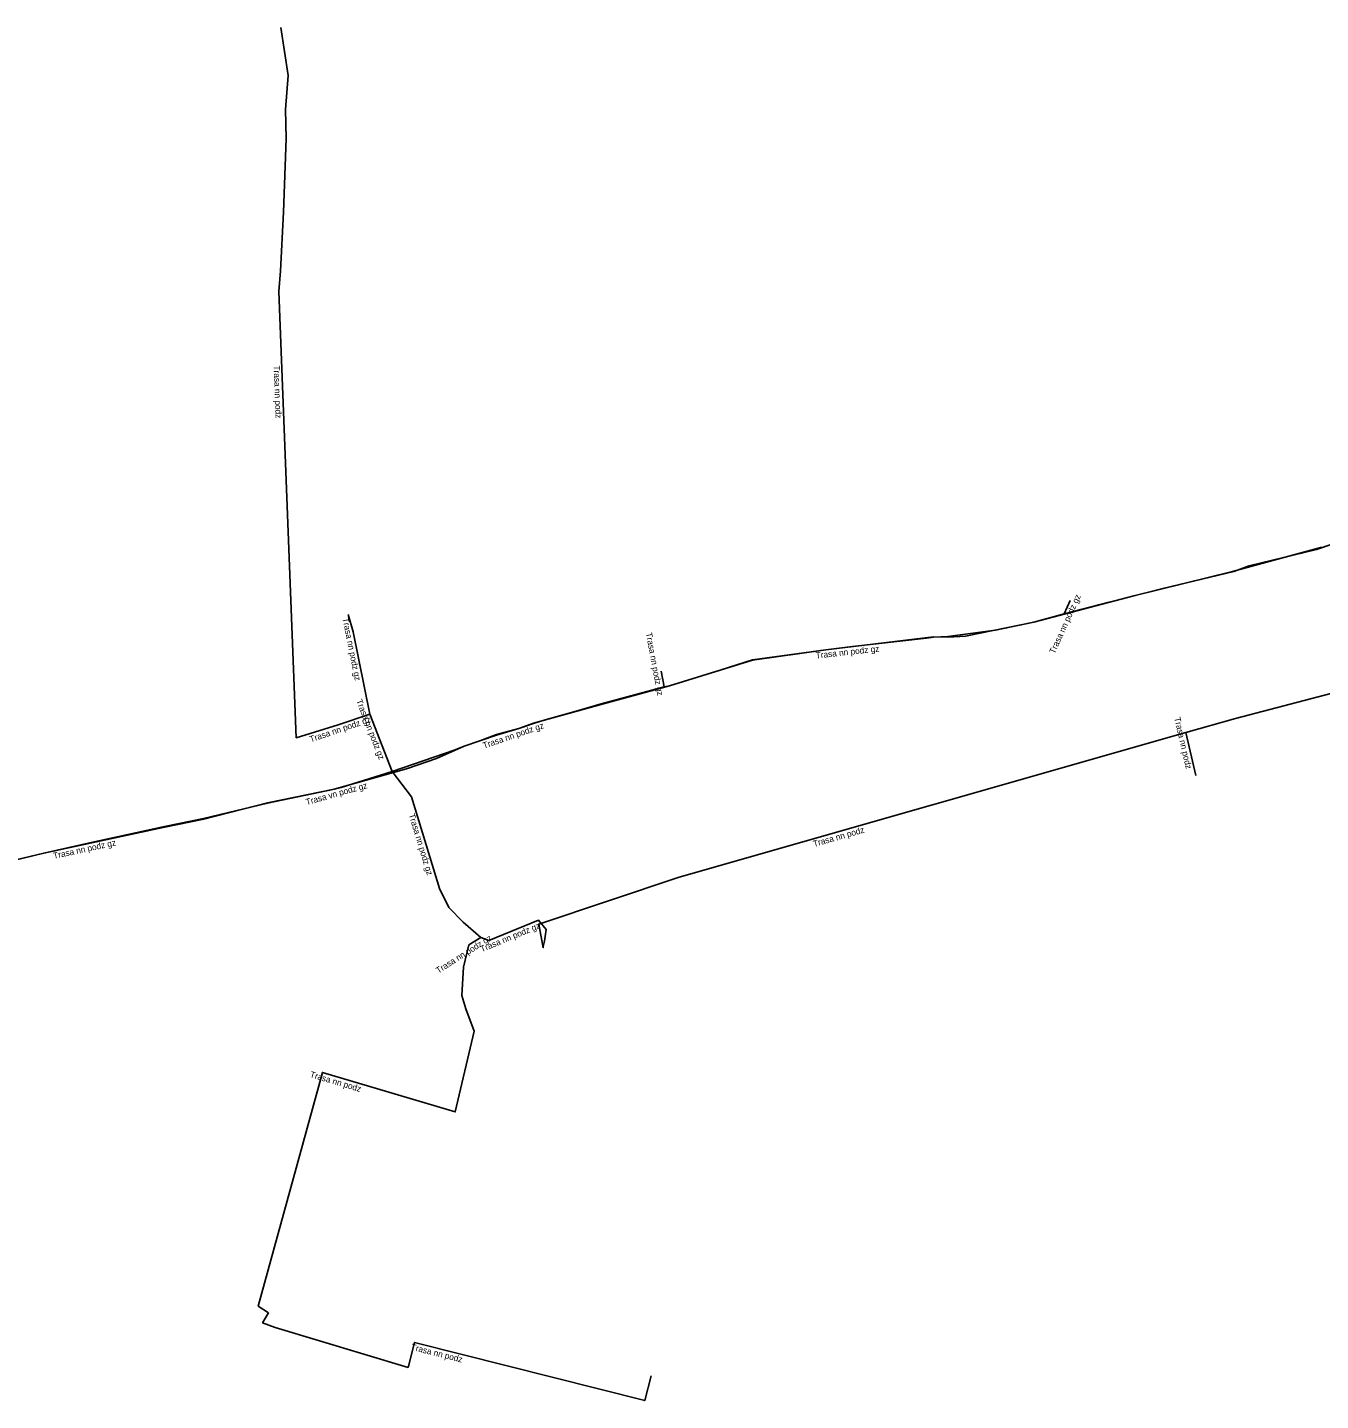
# Model space of a CAD drawing. Extents: x -687924 to -686708, y -1056742 to -1056249.
# Drawn here: x -687824.2 to -687719.7, y -1056710.5 to -1056599.6 of the extents above; entities that cross this region are included whole.
import ezdxf

# ---------------------------------------------------------------- set-up
doc = ezdxf.new("R2010")
doc.units = 0
for name, color, linetype in [('Popiskový text - Ostatní atributy Trasy', 7, 'Continuous'), ('Spojnice NN', 7, 'Continuous'), ('Spojnice VN', 7, 'Continuous')]:
    doc.layers.add(name, color=color, linetype=linetype)

msp = doc.modelspace()

# ---------------------------------------------------------------- linework, layer by layer
at = {"layer": 'Spojnice NN'}
for points in [[(-687799.08, -1056655.9), (-687802.46, -1056656.95), (-687803.87, -1056620.89), (-687803.74, -1056619.22), (-687803.5, -1056614.48), (-687803.26, -1056608.52), (-687803.32, -1056606.19), (-687803.1, -1056603.42), (-687803.69, -1056599.55)], [(-687681.8, -1056630.14), (-687686.32, -1056631.34), (-687692.99, -1056633.26), (-687698.53, -1056635), (-687701.46, -1056635.96), (-687707.22, -1056637.63), (-687711.08, -1056638.91), (-687713.76, -1056639.84), (-687717.6, -1056640.89), (-687720.05, -1056641.72), (-687725.49, -1056643.05), (-687726.71, -1056643.5), (-687732.46, -1056644.89), (-687736.79, -1056645.99), (-687740.43, -1056646.92)], [(-687730.6, -1056656.52), (-687726.58, -1056655.38), (-687702.24, -1056649), (-687678.29, -1056641.75), (-687677.6, -1056641.33)], [(-687740.43, -1056646.92), (-687739.94, -1056645.85)], [(-687796.51, -1056655.03), (-687797.85, -1056648.38), (-687798.26, -1056646.98)], [(-687772.75, -1056652.83), (-687772.31, -1056652.74), (-687768.14, -1056651.45), (-687765.59, -1056650.66), (-687759.69, -1056649.83), (-687757.52, -1056649.57), (-687751.56, -1056648.9), (-687750.98, -1056648.83), (-687749.82, -1056648.77), (-687745.97, -1056648.25), (-687742.89, -1056647.6), (-687740.43, -1056646.92)], [(-687772.75, -1056652.83), (-687772.99, -1056651.57)], [(-687794.7, -1056659.66), (-687789.62, -1056657.92), (-687788.9, -1056657.62), (-687787.62, -1056657.2), (-687786.27, -1056656.74), (-687784.49, -1056656.19), (-687783.29, -1056655.78), (-687782.34, -1056655.5), (-687780.03, -1056654.85), (-687777.65, -1056654.16), (-687776.43, -1056653.82), (-687772.75, -1056652.83)], [(-687799.08, -1056655.9), (-687796.51, -1056655.03)], [(-687796.51, -1056655.03), (-687794.7, -1056659.66)], [(-687782.51, -1056673.81), (-687782.51, -1056673.91), (-687782.86, -1056672.01), (-687771.53, -1056668.21), (-687730.6, -1056656.52)], [(-687730.6, -1056656.52), (-687729.8, -1056660)], [(-687842.07, -1056670.49), (-687840.06, -1056670.06), (-687837.35, -1056669.94), (-687836.75, -1056669.89), (-687836.22, -1056669.72), (-687832.57, -1056668.56), (-687832.25, -1056668.48), (-687828.65, -1056667.65), (-687825.66, -1056666.94), (-687822.85, -1056666.26), (-687819.01, -1056665.42), (-687813.09, -1056664.12), (-687809.94, -1056663.47), (-687804.77, -1056662.22), (-687799.38, -1056661.1), (-687798.84, -1056660.96), (-687794.7, -1056659.66)], [(-687794.7, -1056659.66), (-687793.14, -1056661.73), (-687790.88, -1056669.13), (-687790.13, -1056670.66), (-687788.97, -1056671.84), (-687787.56, -1056673.08)], [(-687782.51, -1056673.81), (-687782.4, -1056673.37), (-687782.28, -1056672.44), (-687782.89, -1056671.68), (-687786.9, -1056673.34), (-687787.56, -1056673.08)], [(-687787.56, -1056673.08), (-687788.51, -1056673.68)], [(-687804.69, -1056703.42), (-687805.53, -1056702.88), (-687800.34, -1056683.99), (-687789.61, -1056687.18), (-687788.08, -1056680.66), (-687788.76, -1056678.86), (-687789.07, -1056677.78), (-687788.94, -1056675.47), (-687788.51, -1056673.68)], [(-687773.8, -1056708.5), (-687774.3, -1056710.5), (-687792.9, -1056705.8), (-687793.43, -1056707.83), (-687804.15, -1056704.61), (-687805.17, -1056704.22), (-687804.69, -1056703.42)]]:
    msp.add_lwpolyline(points, dxfattribs=at)
at = {"layer": 'Spojnice VN'}
msp.add_lwpolyline([(-687828.65, -1056667.68), (-687822.85, -1056666.28), (-687813.21, -1056664.19), (-687809.93, -1056663.52), (-687804.77, -1056662.2), (-687799.39, -1056661.09), (-687793.56, -1056659.45), (-687791.12, -1056658.61), (-687788.9, -1056657.62), (-687787.63, -1056657.19), (-687786.29, -1056656.67), (-687784.49, -1056656.19), (-687783.29, -1056655.77), (-687777.64, -1056654.21), (-687772.31, -1056652.76), (-687765.6, -1056650.68), (-687759.69, -1056649.83), (-687750.98, -1056648.8), (-687749.81, -1056648.83), (-687748.4, -1056648.74), (-687742.89, -1056647.6), (-687734.79, -1056645.48), (-687726.82, -1056643.52), (-687719.62, -1056641.55)], dxfattribs=at)

# ---------------------------------------------------------------- texts
at = {"layer": 'Popiskový text - Ostatní atributy Trasy'}
for s, rotation, p in [('Trasa nn podz', 272.2392, (-687804.29, -1056626.87)), ('Trasa nn podz gz', 65.5803, (-687741.2, -1056650.2)), ('Trasa nn podz gz', 281.426, (-687798.73, -1056647.3)), ('Trasa nn podz gz', 280.5126, (-687774.22, -1056648.49)), ('Trasa nn podz gz', 6.3624, (-687760.47, -1056650.55)), ('Trasa nn podz gz', 291.2964, (-687797.63, -1056653.95)), ('Trasa nn podz gz', 18.6798, (-687801.28, -1056657.32)), ('Trasa nn podz', 282.9465, (-687731.54, -1056655.34)), ('Trasa nn podz gz', 18.8819, (-687787.29, -1056657.83)), ('Trasa vn podz gz', 15.6773, (-687801.61, -1056662.39)), ('Trasa nn podz gz', 286.9645, (-687793.38, -1056663.16)), ('Trasa nn podz', 15.9398, (-687760.63, -1056665.77)), ('Trasa nn podz gz', 12.3107, (-687822.03, -1056666.74)), ('Trasa nn podz gz', 22.487, (-687787.47, -1056674.28)), ('Trasa nn podz gz', 32.2689, (-687790.98, -1056676.01)), ('Trasa nn podz', 343.4429, (-687801.39, -1056684.36)), ('Trasa nn podz', 345.8189, (-687793.24, -1056706.39))]:
    msp.add_text(s, height=0.5, rotation=rotation, dxfattribs=at).set_placement(p)

doc.saveas('drawing.dxf')
